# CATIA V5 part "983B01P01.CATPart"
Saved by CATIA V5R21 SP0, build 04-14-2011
Part number: 983B01P01
Bounding box of the stored display mesh (mm): x -33.399 to 33.399, y -100 to 100, z -8 to 8
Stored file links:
  C:\Users\ALI OZGUN\Desktop\alhan\983B01P01.CATPart
  C:\Users\ALI OZGUN\Desktop\alhan\943B01P01.CATPart
  C:\Users\ALI OZGUN\Desktop\alhan\950B01P01.CATPart
  C:\Users\ALI OZGUN\Desktop\alhan\Product1.CATProduct
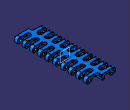
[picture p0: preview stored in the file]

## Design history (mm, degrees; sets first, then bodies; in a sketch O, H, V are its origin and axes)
Set1
  Sketch1 on xy-plane, origin (0, 0, 0), H (1, 0, 0), V (0, 1, 0)
    line L1 (-83.1868, 139.5529) -> (65.3176, 139.5529)
    line L2 (65.3176, 139.5529) -> (65.3176, -131.6519)
    line L3 (65.3176, -131.6519) -> (-83.1868, -131.6519)
    line L4 (-83.1868, -131.6519) -> (-83.1868, 139.5529)
    horizontal: L1 H, L3 H
    vertical: L2 V, L4 V
  Fill1: Boundary Sketch1
Body1 (main body)
Body2
  Sketch2 on zx-plane, origin (0, 0, 0), H (-1, 0, 0), V (0, 0, 1)
    construction line L1 (25.4, 8) -> (25.4, -8)
    line L2 (25.4, -8) -> (-25.4, -8)
    construction line L3 (-25.4, -8) -> (-25.4, 8)
    line L4 (-25.4, 8) -> (25.4, 8)
    point P3 (-25.4, -8)
    arc A1 centre (25.4, 0) radius 8 from (25.4, 8) to (25.4, -8) cw
    arc A2 centre (-25.4, 0) radius 8 from (-25.4, 8) to (-25.4, -8) ccw
    point P7 (-25.4, -8)
    length L4 = 50.8
    length L3 = 16
    vertical: L1 V, L3 V
    horizontal: L2 H, L4 H
    equidistance: L1 L3 O, L2 L4 O
    tangency: A1 L2, A2 L4, A2 L2, L4 A1
    coincidence: P7 L2, P3 P7
  Pad1: profile Sketch2, direction (0, 1, 0), length 100, mirrored extent
  Sketch3 on zx-plane, origin (0, 0, 0), H (-1, 0, 0), V (0, 0, 1)
    circle A1 centre (25.4, 0) radius 3.15
    circle A2 centre (-25.4, 0) radius 3.15
  Pocket1: profile Sketch3, direction (0, -1, 0), length 204, mirrored extent
  Body3 "aramesefa"
    Sketch4 on face of Pad1 from Sketch2.L4, origin (0, 0, 8), H (1, 0, 0), V (0, 1, 0)
      line L1 (21.5, -80) -> (55.8232, -80)
      line L2 (55.8232, -80) -> (55.8232, -90.5)
      line L3 (55.8232, -90.5) -> (21.5, -90.5)
      line L4 (21.5, -90.5) -> (21.5, -80)
      reference projected line E1 (-25.4, -100) -> (25.4, -100) from edge [start face of Pad1 | face of Pad1 from Sketch2.L4]
      line L5 (-54.1233, -90) -> (-21.5, -90)
      line L6 (-21.5, -90) -> (-21.5, -100.5)
      line L7 (-21.5, -100.5) -> (-54.1233, -100.5)
      line L8 (-54.1233, -100.5) -> (-54.1233, -90)
      reference projected line E2 (-25.4, -100) -> (25.4, -100) from edge [start face of Pad1 | face of Pad1 from Sketch2.L4]
      distance L1 L3 = 10.5
      distance L3 E1 = 9.5
      distance L4 V = 21.5
      distance L5 L3 = 0.5
      distance L7 E2 = 0.5
      distance L6 L4 = 43
      horizontal: L1 H, L3 H, L5 H, L7 H
      vertical: L2 V, L4 V, L6 V, L8 V
    Pad2: profile Sketch4, direction (0, 0, 1), length 20, mirrored extent
    RectPattern1: of the body so far, direction 1 instances 10, spacing 20, along yz-plane
  Remove1: tool Body3
  Body4 "ALTBOSLUK"
    Sketch5 on zx-plane, origin (0, 0, 0), H (-1, 0, 0), V (0, 0, 1)
      line L1 (48.9583, 0) -> (33.4, 0)
      arc A1 centre (25.4, 0) radius 8 from (17.4, 0) to (33.4, 0) ccw
      line L2 (17.4, 0) -> (17.4, 0.2)
      arc A2 centre (15.4, 0.2) radius 2 from (17.4, 0.2) to (15.4, 2.2) ccw
      line L3 (15.4, 2.2) -> (5.5215, 2.2)
      arc A3 centre (5.5215, 0.2) radius 2 from (5.5215, 2.2) to (3.5325, 0.4091) ccw
      line L4 (3.5325, 0.4091) -> (2.9836, -4.8136)
      arc A4 centre (0, -4.4996) radius 3 from (-2.9836, -4.8136) to (2.9836, -4.8136) ccw
      line L5 (-2.9836, -4.8136) -> (-3.5325, 0.4091)
      arc A5 centre (-5.5215, 0.2) radius 2 from (-3.5325, 0.4091) to (-5.5215, 2.2) ccw
      line L6 (-5.5215, 2.2) -> (-15.4, 2.2)
      arc A6 centre (-15.4, 0.2) radius 2 from (-15.4, 2.2) to (-17.4, 0.2) ccw
      line L7 (-17.4, 0.2) -> (-17.4, 0)
      arc A7 centre (-25.4, 0) radius 8 from (-33.4, 0) to (-17.4, 0) ccw
      line L8 (-33.4, 0) -> (-46.3888, 0)
      line L9 (-46.3888, 0) -> (-46.3888, -17.807)
      line L10 (-46.3888, -17.807) -> (48.9583, -17.807)
      line L11 (48.9583, -17.807) -> (48.9583, 0)
      vertical: L9 V, L11 V
      horizontal: L10 H
    Pad3: profile Sketch5, direction (0, 1, 0), length 215, mirrored extent
  Remove2: tool Body4
  Body5 "KALANTIBOSALTMA"
    Sketch6 on face of Pad1 from Sketch2.L4, origin (0, 0, 8), H (1, 0, 0), V (0, 1, 0)
      line L1 (10, -80) -> (55.8232, -80)
      line L2 (55.8232, -80) -> (55.8232, -90.5)
      line L3 (55.8232, -90.5) -> (10, -90.5)
      line L4 (10, -90.5) -> (10, -80)
      reference projected line E1 (-25.4, -100) -> (25.4, -100) from edge [start face of Pad1 | face of Pad1 from Sketch2.L4]
      line L5 (-54.1233, -90) -> (-10, -90)
      line L6 (-10, -90) -> (-10, -100.5)
      line L7 (-10, -100.5) -> (-54.1233, -100.5)
      line L8 (-54.1233, -100.5) -> (-54.1233, -90)
      reference projected line E2 (-25.4, -100) -> (25.4, -100) from edge [start face of Pad1 | face of Pad1 from Sketch2.L4]
      distance L1 L3 = 10.5
      distance L3 E1 = 9.5
      distance L4 V = 10
      distance L5 L3 = 0.5
      distance L7 E2 = 0.5
      distance L6 L4 = 20
      horizontal: L1 H, L3 H, L5 H, L7 H
      vertical: L2 V, L4 V, L6 V, L8 V
    Pad4: profile Sketch6, direction (0, 0, 1), length 20, mirrored extent
    RectPattern2: of the body so far, direction 1 instances 10, spacing 20, along yz-plane
    Sketch7 on zx-plane, origin (0, 0, 0), H (-1, 0, 0), V (0, 0, 1)
      line L1 (108.0577, 2.2) -> (-84.5523, 2.2)
      fix: L1
    Pocket2: profile Sketch7, direction (0, -1, 0), length 215, mirrored extent
  Remove3: tool Body5
  Body6 "aramesefa ACILARI"
    Sketch8 on face of Pad1 from Sketch2.L4, origin (0, 0, 8), H (1, 0, 0), V (0, 1, 0)
      line L1 (21.5, -80) -> (55.8232, -80)
      line L2 (55.8232, -80) -> (55.8232, -90.5)
      line L3 (55.8232, -90.5) -> (21.5, -90.5)
      line L4 (21.5, -90.5) -> (21.5, -80)
      reference projected line E1 (-25.4, -100) -> (25.4, -100) from edge [start face of Pad1 | face of Pad1 from Sketch2.L4]
      line L5 (-54.1233, -90) -> (-21.5, -90)
      line L6 (-21.5, -90) -> (-21.5, -100.5)
      line L7 (-21.5, -100.5) -> (-54.1233, -100.5)
      line L8 (-54.1233, -100.5) -> (-54.1233, -90)
      reference projected line E2 (-25.4, -100) -> (25.4, -100) from edge [start face of Pad1 | face of Pad1 from Sketch2.L4]
      distance L1 L3 = 10.5
      distance L3 E1 = 9.5
      distance L4 V = 21.5
      distance L5 L3 = 0.5
      distance L7 E2 = 0.5
      distance L6 L4 = 43
      horizontal: L1 H, L3 H, L5 H, L7 H
      vertical: L2 V, L4 V, L6 V, L8 V
    Pad5: profile Sketch8, direction (0, 0, 1), length 20, mirrored extent
    Sketch9 on zx-plane, origin (0, 0, 0), H (-1, 0, 0), V (0, 0, 1)
      line L1 (67.6223, 8) -> (-70.015, 8)
      fix: L1
    Pocket3: profile Sketch9, direction (0, -1, 0), length 215, mirrored extent
    Draft1: Angle 45, Neutral face of Pocket3 from Sketch9.L1, PullDir face of Pocket3 from Sketch9.L1, SupportToDraft face of Pad5 from Sketch8.L6
    Draft2: Angle 45, Neutral face of Pocket3 from Sketch9.L1, PullDir face of Pocket3 from Sketch9.L1, SupportToDraft face of Pad5 from Sketch8.L4
    RectPattern3: of the body so far, direction 1 instances 10, spacing 20, along yz-plane
  Remove4: tool Body6
  Sketch10 on zx-plane, origin (0, 0, 0), H (-1, 0, 0), V (0, 0, 1)
    line L1 (0, 72) -> (0, 6.9718)
    point P1 (0, 72)
    reference projected line E1 (-25.4, -8) -> (25.4, -8) from edge [face of Pad1 from Sketch2.L2 | end face of Pad1]
    distance P1 E1 = 80
    coincidence: P1 V
    vertical: L1 V
  Sketch11 on face of Pad1 from Sketch2.L4, origin (0, 0, 8), H (1, 0, 0), V (0, 1, 0)
    projected line E1 (21.5, -80) -> (21.5, -90.5) from edge [face of Pad1 from Sketch2.L4 | face of Pad5 from Sketch8.L4]
    projected line E2 (-21.5, -100) -> (-21.5, -90) from edge [face of Pad1 from Sketch2.L4 | face of Pad5 from Sketch8.L6]
    construction line L1 (21.5, -85.25) -> (44.0665, -85.25)
    point P5 (21.5, -85.25)
    axis line L2 (-21.5, -95.25) -> (-49.708, -95.25)
    construction line L3 (10.25, -85.25) -> (51.2195, -85.25)
    point P9 (10.25, -85.25)
    line L4 (10.25, -80) -> (51.2195, -80)
    line L5 (51.2195, -90.5) -> (10.25, -90.5)
    arc A1 centre (51.2195, -85.25) radius 5.25 from (51.2195, -80) to (51.2195, -90.5) cw
    arc A2 centre (10.25, -85.25) radius 5.25 from (10.25, -90.5) to (10.25, -80) cw
    construction line L6 (-10.25, -95.25) -> (-53.4024, -95.25)
    point P15 (-10.25, -95.25)
    line L7 (-10.25, -100.5) -> (-53.4024, -100.5)
    line L8 (-53.4024, -90) -> (-10.25, -90)
    arc A3 centre (-53.4024, -95.25) radius 5.25 from (-53.4024, -100.5) to (-53.4024, -90) cw
    arc A4 centre (-10.25, -95.25) radius 5.25 from (-10.25, -90) to (-10.25, -100.5) cw
    distance L3 L4 = 5.25
    distance L6 L7 = 5.25
    distance A4 A2 H = 10
    distance A4 V = 5
    distance L8 L5 = 0.5
    midpoint: P5 E1
    horizontal: L1 H, L2 H, L3 H, L6 H
    coincidence: P9 L1, P15 L2
    tangency: A1 L4, A2 L4, A1 L5, A2 L5, A3 L7, A4 L7, A3 L8, A4 L8
  Pocket4: profile Sketch11, direction (0, 0, -1), length 215
  RectPattern4: of Pocket4, direction 1 instances 10, spacing 20, along axis of face of Pad1
  Sketch12 on face of Pad1 from Sketch2.L4, origin (0, 0, 8), H (1, 0, 0), V (0, 1, 0)
    projected arc E1 centre (-10.25, -95.25) radius 5.25 from (-8.0139, -100) to (-10.25, -90) ccw from edge [face of Pad1 from Sketch2.L4 | face of Pocket4 from Sketch11.A4]
    projected arc E2 centre (-10.25, -95.25) radius 5.25 from (-5, -95.25) to (-10.25, -90) ccw from edge [face of Pad1 from Sketch2.L4 | face of Pocket4 from Sketch11.A4]
    line L1 (-5, -95.25) -> (-5, -103.1639)
    line L2 (5, 94.75) -> (5, 102.6639)
    construction arc A1 centre (10.25, 94.75) radius 5.25 from (8.6492, 99.75) to (10.25, 89.5) ccw
    arc A2 centre (10.25, 94.75) radius 5.25 from (5, 94.75) to (10.25, 89.5) ccw
    reference projected arc E3 centre (10.25, 94.75) radius 5.25 from (10.25, 100) to (10.25, 89.5) ccw from edge [face of Pad1 from Sketch2.L4 | face of RectPattern4]
    line L3 (5, 102.6639) -> (52.4098, 102.6639)
    line L4 (52.4098, 102.6639) -> (52.4098, 89.5)
    line L5 (52.4098, 89.5) -> (10.25, 89.5)
    line L6 (-10.25, -90) -> (-62.5817, -90)
    line L7 (-62.5817, -90) -> (-62.5817, -103.1639)
    line L8 (-62.5817, -103.1639) -> (-5, -103.1639)
    distance L2 V = 5
    vertical: L1 V, L4 V, L7 V
    tangency: L1 E1, L2 A2, L5 A1, L6 E1
    concentricity: A2 E3
    horizontal: L3 H, L8 H
  Pocket5: profile Sketch12, direction (0, 0, -1), length 215
  Draft3: Angle 13, Neutral Fill1, PullDir Fill1, SupportToDraft (start face of Pad1; face of Pocket4; face of RectPattern4; face of RectPattern4; face of RectPattern4; face of Pocket4; face of RectPattern4; face of RectPattern4; face of RectPattern4; face of RectPattern4; face of RectPattern4; face of RectPattern4; face of RectPattern4; face of Pocket5; face of RectPattern4; face of RectPattern4; face of RectPattern4; face of RectPattern4; face of RectPattern4; face of RectPattern4; face of Pocket5; face of RectPattern4; face of RectPattern4; face of RectPattern4; face of RectPattern4; face of RectPattern4; face of RectPattern4; face of RectPattern4; face of RectPattern4; face of RectPattern4; face of RectPattern4; face of RectPattern4; face of RectPattern4; face of RectPattern4; face of RectPattern4; face of RectPattern4; face of RectPattern4; face of RectPattern4; face of RectPattern4; end face of Pad1)
  RemoveFace1: RemoveFaces (end face of Pad1; start face of Pad1)
  Fillet1: radius 1, on edge [face of Pad1 from Sketch2.L4 | face of RectPattern4] (x16); face of RectPattern4 (x2); edge [face of Pad1 from Sketch2.L4 | face of Pocket4 from Sketch11.A2]; edge [face of Pocket5 from Sketch12.L2 | end face of Pad1]; edge [face of Pad1 from Sketch2.L4 | face of Pocket5 from Sketch12.L2]; edge [face of Pad1 from Sketch2.L4 | end face of Pad1]; edge [face of Pad1 from Sketch2.L4 | face of Pocket5]; edge [face of Pocket5 from Sketch12.L1 | start face of Pad1]; edge [start face of Pad1 | face of Pad1 from Sketch2.L4]; edge [end face of Pad1 | face of Pad1]; edge [end face of Pad1 | face of Pad3]; edge [end face of Pad1 | face of Pad3 from Sketch5.L4]; edge [face of RectPattern4 | face of Pad1] (x24); edge [face of Pocket5 | face of Pad1]; edge [face of RectPattern4 | face of Pad3] (x7); edge [face of RectPattern4 | face of Pad3 from Sketch5.A1] (x3); edge [face of Pad3 | face of Pocket5]; edge [start face of Pad1 | face of Pad3 from Sketch5.A4]; edge [face of Pad3 from Sketch5.A3 | start face of Pad1]; edge [face of Pad3 | start face of Pad1]; edge [start face of Pad1 | face of Pad3 from Sketch5.A7]; edge [face of Pocket4 | face of Pad3 from Sketch5.A7]; edge [face of RectPattern4 | face of Pad3 from Sketch5.A7] (x4); edge [face of Pocket4 | face of Pad3 from Sketch5.A6]; edge [face of Pad3 | face of RectPattern4] (x5); edge [face of Pocket5 | face of Pad3 from Sketch5.A7]; edge [face of Pocket5 | face of Pad3]; edge [end face of Pad1 | face of Pad3 from Sketch5.A5]; edge [face of RectPattern4 | face of Pad3 from Sketch5.A3] (x3); edge [face of Pocket4 | face of Pad1]
Body7
  Solid1: linked copy from another document
  Translate1: Direction yz-plane, Length 50.8, ToTransfor Solid1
